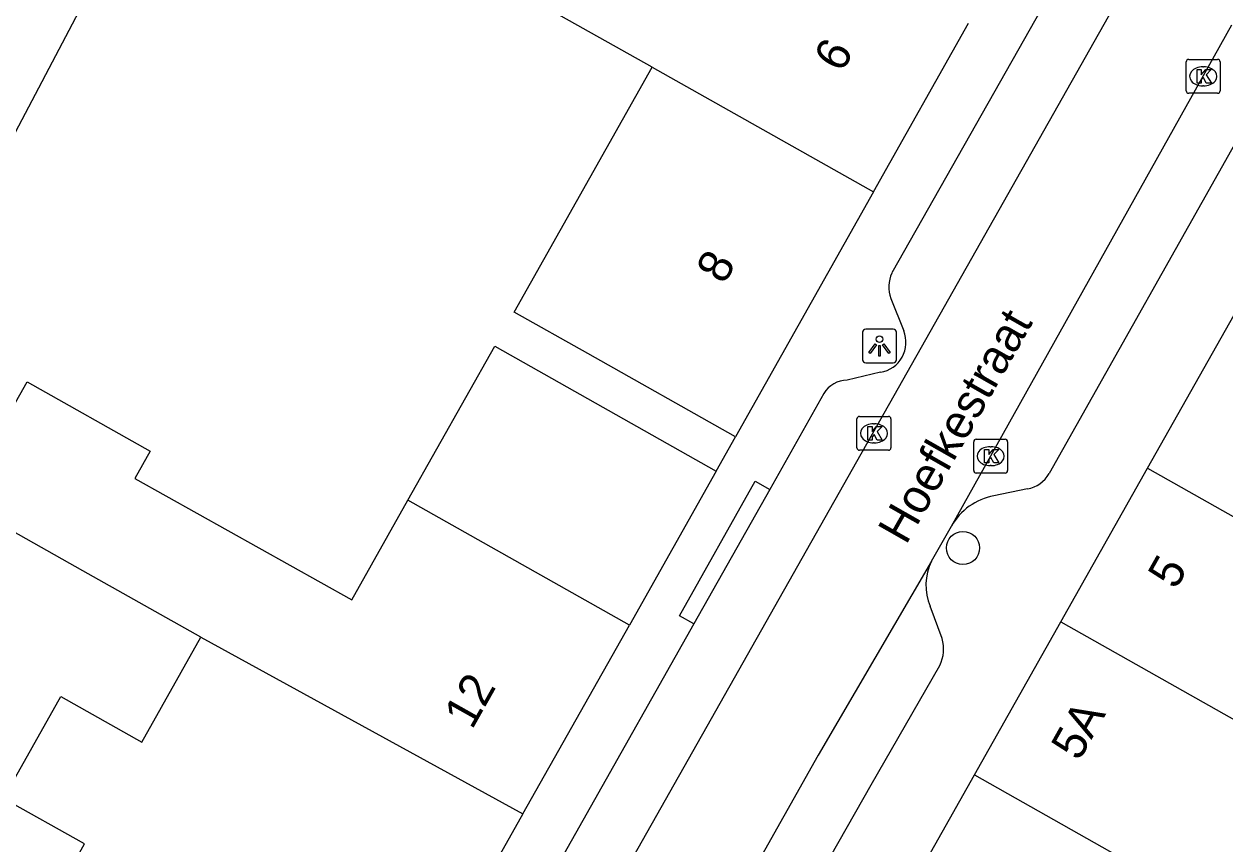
# Model space of a CAD drawing. Extents: x 161801 to 162379, y 382315 to 382832.
# Drawn here: x 161994.64 to 162030.05, y 382663.73 to 382687.91 of the extents above; entities that cross this region are included whole.
import ezdxf

# ---------------------------------------------------------------- set-up
doc = ezdxf.new("R2010")
doc.units = 0
for name, color, linetype in [('IMGEO_Boom', 7, 'Continuous'), ('IMGEO_Kolk', 7, 'Continuous'), ('IMGEO_Lichtpunt', 7, 'Continuous'), ('IMGEO_Openbare_ruimte_label', 7, 'Continuous'), ('IMGEO_Pand', 7, 'Continuous'), ('IMGEO_Pand_nummerreeks', 7, 'Continuous'), ('IMGEO_Rijbaan_lokaal_open', 7, 'Continuous'), ('IMGEO_Voetpad_open', 7, 'Continuous')]:
    doc.layers.add(name, color=color, linetype=linetype)

msp = doc.modelspace()

# ---------------------------------------------------------------- linework, layer by layer
at = {"layer": 'IMGEO_Boom'}
msp.add_circle((162022.324, 382672.456), 0.489, dxfattribs=at)
at = {"layer": 'IMGEO_Kolk'}
for p, q in [((162028.982, 382686.864), (162029.834, 382686.864)), ((162028.907, 382685.938), (162028.907, 382686.79)), ((162029.395, 382686.644), (162029.42, 382686.644)), ((162029.908, 382686.79), (162029.908, 382685.938)), ((162029.834, 382685.864), (162028.982, 382685.864)), ((162029.418, 382686.084), (162029.393, 382686.084)), ((162019.199, 382675.411), (162019.199, 382676.263)), ((162019.274, 382676.337), (162020.126, 382676.337)), ((162020.2, 382676.263), (162020.2, 382675.411)), ((162019.687, 382676.117), (162019.712, 382676.117)), ((162019.71, 382675.557), (162019.685, 382675.557)), ((162022.64, 382674.737), (162022.64, 382675.589)), ((162022.715, 382675.663), (162023.567, 382675.663)), ((162023.641, 382675.589), (162023.641, 382674.737)), ((162020.126, 382675.337), (162019.274, 382675.337)), ((162023.128, 382675.443), (162023.153, 382675.443)), ((162023.151, 382674.883), (162023.126, 382674.883)), ((162023.567, 382674.663), (162022.715, 382674.663))]:
    msp.add_line(p, q, dxfattribs=at)
for points in [[(162028.982, 382686.864), (162029.834, 382686.864)], [(162028.907, 382685.938), (162028.907, 382686.79)], [(162029.228, 382686.564), (162029.351, 382686.564), (162029.351, 382686.413), (162029.481, 382686.564), (162029.645, 382686.564), (162029.499, 382686.413), (162029.652, 382686.164), (162029.5, 382686.164), (162029.415, 382686.328), (162029.351, 382686.261), (162029.351, 382686.164), (162029.228, 382686.164), (162029.228, 382686.564)], [(162029.908, 382686.79), (162029.908, 382685.938)], [(162029.834, 382685.864), (162028.982, 382685.864)], [(162019.199, 382675.411), (162019.199, 382676.263)], [(162019.274, 382676.337), (162020.126, 382676.337)], [(162020.2, 382676.263), (162020.2, 382675.411)], [(162019.52, 382676.037), (162019.643, 382676.037), (162019.643, 382675.886), (162019.773, 382676.037), (162019.937, 382676.037), (162019.791, 382675.886), (162019.944, 382675.637), (162019.792, 382675.637), (162019.707, 382675.801), (162019.643, 382675.734), (162019.643, 382675.637), (162019.52, 382675.637), (162019.52, 382676.037)], [(162022.64, 382674.737), (162022.64, 382675.589)], [(162022.715, 382675.663), (162023.567, 382675.663)], [(162023.641, 382675.589), (162023.641, 382674.737)], [(162020.126, 382675.337), (162019.274, 382675.337)], [(162022.961, 382675.363), (162023.084, 382675.363), (162023.084, 382675.212), (162023.214, 382675.363), (162023.378, 382675.363), (162023.232, 382675.212), (162023.385, 382674.963), (162023.233, 382674.963), (162023.148, 382675.127), (162023.084, 382675.06), (162023.084, 382674.963), (162022.961, 382674.963), (162022.961, 382675.363)], [(162023.567, 382674.663), (162022.715, 382674.663)]]:
    msp.add_lwpolyline(points, dxfattribs=at)
for centre, start, end in [((162028.984, 382686.788), 91.552, 178.448), ((162028.984, 382686.788), 91.552, 178.448), ((162029.832, 382686.788), 1.552, 88.448), ((162029.832, 382686.788), 1.552, 88.448), ((162028.984, 382685.94), 181.552, 268.448), ((162028.984, 382685.94), 181.552, 268.448), ((162029.832, 382685.94), 271.552, 358.448), ((162029.832, 382685.94), 271.552, 358.448), ((162019.276, 382676.261), 91.552, 178.448), ((162019.276, 382676.261), 91.552, 178.448), ((162020.124, 382676.261), 1.552, 88.448), ((162020.124, 382676.261), 1.552, 88.448), ((162022.717, 382675.587), 91.552, 178.448), ((162022.717, 382675.587), 91.552, 178.448), ((162023.565, 382675.587), 1.552, 88.448), ((162023.565, 382675.587), 1.552, 88.448), ((162019.276, 382675.413), 181.552, 268.448), ((162019.276, 382675.413), 181.552, 268.448), ((162020.124, 382675.413), 271.552, 358.448), ((162020.124, 382675.413), 271.552, 358.448), ((162022.717, 382674.739), 181.552, 268.448), ((162022.717, 382674.739), 181.552, 268.448), ((162023.565, 382674.739), 271.552, 358.448), ((162023.565, 382674.739), 271.552, 358.448)]:
    msp.add_arc(centre, 0.0765, start, end, dxfattribs=at)
for centre, major_axis, ratio, start_param, end_param in [((162029.394, 382686.364), (-0.387, 0.002), 0.722429, 4.712389, 7.853982), ((162029.419, 382686.364), (-0.39, 0.002), 0.717154, 1.570796, 4.712389), ((162019.686, 382675.837), (-0.387, 0.002), 0.722429, 4.712389, 7.853982), ((162019.711, 382675.837), (-0.39, 0.002), 0.717154, 1.570796, 4.712389), ((162023.127, 382675.163), (-0.387, 0.002), 0.722429, 4.712389, 7.853982), ((162023.152, 382675.163), (-0.39, 0.002), 0.717154, 1.570796, 4.712389)]:
    msp.add_ellipse(centre, major_axis=major_axis, ratio=ratio, start_param=start_param, end_param=end_param, dxfattribs=at)
at = {"layer": 'IMGEO_Lichtpunt'}
for p, q in [((162019.364, 382678.815), (162019.364, 382678.008)), ((162019.364, 382678.815), (162019.364, 382678.008)), ((162020.266, 382678.91), (162019.458, 382678.91)), ((162020.266, 382678.91), (162019.458, 382678.91)), ((162020.36, 382678.008), (162020.36, 382678.815)), ((162020.36, 382678.008), (162020.36, 382678.815)), ((162019.458, 382677.914), (162020.266, 382677.914)), ((162019.458, 382677.914), (162020.266, 382677.914))]:
    msp.add_line(p, q, dxfattribs=at)
for points in [[(162019.738, 382678.479), (162019.777, 382678.451), (162019.589, 382678.189), (162019.551, 382678.216), (162019.738, 382678.479)], [(162019.84, 382678.431), (162019.887, 382678.431), (162019.887, 382678.109), (162019.84, 382678.109), (162019.84, 382678.431)], [(162019.95, 382678.451), (162019.988, 382678.478), (162020.175, 382678.216), (162020.136, 382678.188), (162019.95, 382678.451)]]:
    msp.add_lwpolyline(points, dxfattribs=at)
msp.add_circle((162019.863, 382678.613), 0.0994, dxfattribs=at)
for centre, start, end in [((162019.458, 382678.815), 90, 180), ((162019.458, 382678.815), 90, 180), ((162020.266, 382678.815), 0, 90), ((162020.266, 382678.815), 0, 90), ((162019.458, 382678.008), 180, 270), ((162019.458, 382678.008), 180, 270), ((162020.266, 382678.008), 270, 0), ((162020.266, 382678.008), 270, 360)]:
    msp.add_arc(centre, 0.0946, start, end, dxfattribs=at)
at = {"layer": 'IMGEO_Pand'}
for points in [[(162013.156, 382686.635), (162010.234, 382688.281), (162009.858, 382688.493), (162012.495, 382693.177), (162012.402, 382693.23), (162012.033, 382693.437), (162009.735, 382694.733), (162010.637, 382696.335), (162013.398, 382694.78)], [(162019.684, 382682.959), (162022.485, 382687.932)], [(162015.615, 382675.734), (162011.259, 382678.188), (162009.087, 382679.412), (162013.156, 382686.635)], [(162013.156, 382686.635), (162019.684, 382682.959)], [(162019.684, 382682.959), (162015.615, 382675.734)], [(162027.764, 382674.809), (162030.318, 382679.335)], [(162005.96, 382673.861), (162008.519, 382678.408), (162015.046, 382674.723)], [(161999.855, 382669.821), (161996.369, 382671.782), (161991.572, 382674.481), (161993.128, 382677.244), (161994.296, 382676.587), (161994.729, 382677.355), (161998.358, 382675.314), (161997.905, 382674.509), (162004.308, 382670.928), (162005.96, 382673.861)], [(162025.211, 382670.282), (162027.764, 382674.809)], [(162027.764, 382674.809), (162036.925, 382669.634)], [(162015.046, 382674.723), (162012.489, 382670.184)], [(162012.489, 382670.184), (162005.96, 382673.861)], [(162022.663, 382665.766), (162025.211, 382670.282)], [(162025.211, 382670.282), (162034.369, 382665.109)], [(162009.351, 382664.611), (162012.489, 382670.184)], [(161995.988, 382662.954), (161996.423, 382663.727), (161994.033, 382665.067), (161995.726, 382668.073), (161998.116, 382666.733), (161999.855, 382669.821)], [(161999.855, 382669.821), (162009.351, 382664.611)], [(162020.106, 382661.234), (162022.663, 382665.766)], [(162022.663, 382665.766), (162031.821, 382660.586)], [(162009.351, 382664.611), (162005.425, 382657.64)]]:
    msp.add_lwpolyline(points, dxfattribs=at)
at = {"layer": 'IMGEO_Rijbaan_lokaal_open'}
for points in [[(162008.841, 382656.703), (162030.647, 382695.267)], [(161971, 382658.776), (161974.714, 382658.211), (161977.339, 382656.596), (161992.884, 382681.874), (161999.451, 382694.354)], [(162021.983, 382673.097), (162030.256, 382687.882)], [(162021.396, 382672.067), (162021.983, 382673.097)], [(162021.396, 382672.067), (162018.058, 382666.344), (162015.013, 382660.948), (162011.822, 382655.343), (162011.674, 382655.092)]]:
    msp.add_lwpolyline(points, dxfattribs=at)
at = {"layer": 'IMGEO_Voetpad_open'}
for points in [[(162028.175, 382694.602), (162020.224, 382680.565)], [(162030.633, 382684.899), (162024.865, 382674.648)], [(162020.196, 382679.815), (162020.58, 382678.855)], [(162019.892, 382677.636), (162018.906, 382677.404)], [(162018.224, 382677.013), (162016.625, 382674.182)], [(162015.046, 382674.723), (162015.615, 382675.734)], [(162014.387, 382670.217), (162013.964, 382670.454), (162016.194, 382674.424), (162016.625, 382674.182)], [(162016.625, 382674.182), (162014.387, 382670.217)], [(162024.225, 382674.198), (162023.238, 382673.996)], [(162021.707, 382669.784), (162021.356, 382670.736)], [(162014.387, 382670.217), (162007.838, 382658.619)], [(162014.383, 382656.258), (162016.505, 382659.985), (162019.617, 382665.474), (162021.642, 382668.994)]]:
    msp.add_lwpolyline(points, dxfattribs=at)
for centre, radius, start, end in [((162021.137, 382680.155), 1, 155.8273, 199.8966), ((162019.749, 382678.521), 0.896, 279.2019, 21.9176), ((162018.916, 382676.597), 0.807, 90.6926, 148.9599), ((162024.063, 382675.108), 0.925, 280.0798, 330.1443), ((162023.578, 382672.196), 1.832, 100.6984, 150.5323), ((162022.845, 382671.357), 1.613, 153.9037, 202.6536), ((162020.668, 382669.472), 1.085, 333.8715, 16.7212)]:
    msp.add_arc(centre, radius, start, end, dxfattribs=at)

# ---------------------------------------------------------------- texts
at = {"layer": 'IMGEO_Openbare_ruimte_label'}
msp.add_text('Hoefkestraat', height=1, rotation=60.3333, dxfattribs=at).set_placement((162020.643, 382672.521))
at = {"layer": 'IMGEO_Pand_nummerreeks'}
for s, rotation, p in [('6', 60.6132, (162018.752, 382686.443)), ('8', 60.978, (162015.285, 382680.201)), ('5', 60.5713, (162028.599, 382671.2)), ('12', 60.6132, (162007.846, 382667.073)), ('5A', 60.5713, (162025.746, 382666.143))]:
    msp.add_text(s, height=1, rotation=rotation, dxfattribs=at).set_placement(p)

doc.saveas('drawing.dxf')
